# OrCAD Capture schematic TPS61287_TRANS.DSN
size C
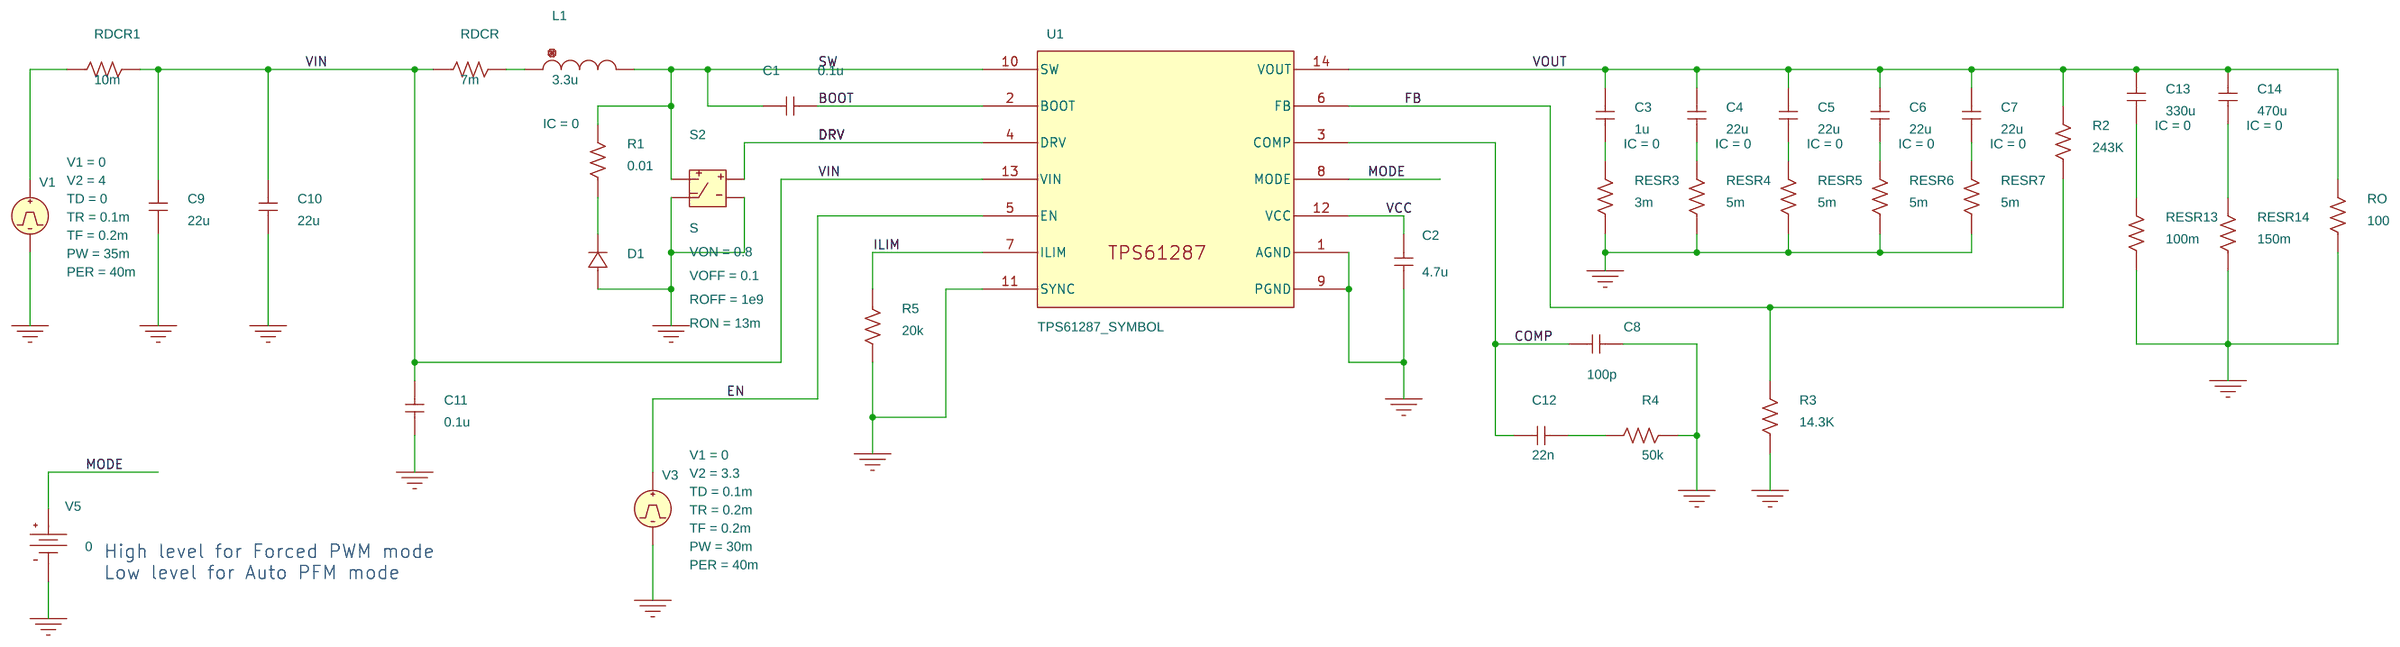
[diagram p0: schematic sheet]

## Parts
C1  0.1u  [RAD/CK05]
C2  4.7u  [RAD/CK05]
C3  1u  [RAD/CK05]
C4  22u  [RAD/CK05]
C5  22u  [RAD/CK05]
C6  22u  [RAD/CK05]
C7  22u  [RAD/CK05]
C8  100p  [RAD/CK05]
C9  22u  [RAD/CK05]
C10  22u  [RAD/CK05]
C11  0.1u  [RAD/CK05]
C12  22n  [RAD/CK05]
C13  330u  [RAD/CK05]
C14  470u  [RAD/CK05]
D1  Dbreak
L1  3.3u  [DISC/.350x.175/LS.200x.100/.034]
R1  0.01  [AX/RC05]
R2  243K  [AX/RC05]
R3  14.3K  [AX/RC05]
R4  50k  [AX/RC05]
R5  20k  [AX/RC05]
RDCR  7m  [AX/RC05]
RDCR1  10m  [AX/RC05]
RESR3  3m  [AX/RC05]
RESR4  5m  [AX/RC05]
RESR5  5m  [AX/RC05]
RESR6  5m  [AX/RC05]
RESR7  5m  [AX/RC05]
RESR13  100m  [AX/RC05]
RESR14  150m  [AX/RC05]
RO  100  [AX/RC05]
S2  S
U1  TPS61287_SYMBOL
V1  VPULSE
V3  VPULSE
V5  VDC

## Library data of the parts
C1 C2 C8-C12 = C
C3-C7 C13 C14 = C: IC: 0
D1 = Dbreak
L1 = L: IC: 0
R1-R5 RDCR RDCR1 RESR3-RESR7 RESR13 RESR14 RO = R
S2 = S: ROFF: 1e9; RON: 13m; VOFF: 0.1; VON: 0.8
U1 = TPS61287_SYMBOL_5
V1 = VPULSE: PER: 40m; PW: 35m; TD: 0; TF: 0.2m; TR: 0.1m; V1: 0; V2: 4
V3 = VPULSE: PER: 40m; PW: 30m; TD: 0.1m; TF: 0.2m; TR: 0.2m; V1: 0; V2: 3.3
V5 = VDC: DC: 0

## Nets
VCC: C2.1 U1.12(VCC)
VIN: C9.2 C10.2 C11.2 RDCR.1 RDCR1.2 U1.13(VIN)
0: C2.2 C8.1 C9.1 C10.1 C11.1 D1.0(1) R3.1 R4.1 R5.2 RESR3.1 RESR4.1 RESR5.1 RESR6.1 RESR7.1 RESR13.1 RESR14.1 RO.1 S2.1(2) S2.3(4) U1.1(AGND) U1.9(PGND) U1.11(SYNC) V1.2(-) V3.2(-) V5.1(-)
BOOT: C1.1 U1.2(BOOT)
COMP: C8.2 C12.2 U1.3(COMP)
DRV: S2.0(1) U1.4(DRV)
EN: U1.5(EN) V3.1(+)
FB: R2.1 R3.2 U1.6(FB)
ILIM: R5.1 U1.7(ILIM)
MODE: U1.8(MODE) V5.0(+)
SW: C1.2 L1.2 R1.2 S2.2(3) U1.10(SW)
VOUT: C3.1 C4.1 C5.1 C6.1 C7.1 C13.1 C14.1 R2.2 RO.2 U1.14(VOUT)
N30074: RDCR1.1 V1.1(+)
N30114: L1.1 RDCR.2
N30416: C13.2 RESR13.2
N30422: C14.2 RESR14.2
N30476: C3.2 RESR3.2
N30482: C4.2 RESR4.2
N30488: C5.2 RESR5.2
N30494: C6.2 RESR6.2
N30500: C7.2 RESR7.2
N30760: D1.1(2) R1.1
N31318: C12.1 R4.2

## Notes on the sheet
- High level for Forced PWM mode
  Low level for Auto PFM mode
